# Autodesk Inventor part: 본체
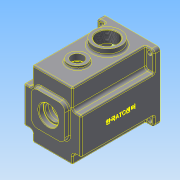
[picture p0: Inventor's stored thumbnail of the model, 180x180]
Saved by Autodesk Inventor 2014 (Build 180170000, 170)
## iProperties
Created: 2016-02
Part Number: 본체
Material: 알루미늄 6061
Document SubType Name: Modeling
Designer: mduedu
Density: 2.71 g/cm^3
Mass: 1353.73 g
Surface Area: 1142.22 cm^2
Volume: 499.531 cm^3
Appearance: 기본값
Author: mduedu
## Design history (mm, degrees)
sketch "스케치1"
  geometry: L1 (-47, -47)-(47, -47); L2 (47, -47)-(47, 63); L3 (47, 63)-(-47, 63); L4 (-47, 63)-(-47, -47); 2 further points
  constraints: 8 end point, 2 parallel, 1 horizontal, 1 midpoint, 1 perpendicular, 1 vertical alignment
  dimensions: "d0" = 94 distance of L2.end L3.end; "d155" = 110 distance of L1.end L2.end; "d156" = 47 distance from line of L1 point (0, 0)
extrude "돌출1" new body sketch "스케치1" distance "d2" = 130; taper "d3" = 0 deg
sketch "스케치3"
  geometry: C1 r 40 at (0, 0); 1 further point
  constraints: 1 centre point, 1 coincident
  dimensions: "d9" = 80 diameter of C1
extrude "돌출3" cut sketch "스케치3" distance "d11" = 121; taper "d12" = 0 deg
sketch "스케치4"
  geometry: C1 r 21 at (0, 11); 1 further point
  constraints: 1 centre point, 1 vertical alignment
  dimensions: "d13" = 21 radius of C1; "d15" = 11 distance of point (0, 0) C1.centre
extrude "돌출4" join sketch "스케치4" distance "d16" = 7; taper "d17" = 0 deg
sketch "스케치5"
  geometry: C1 r 15 at (0, -20); 1 further point
  constraints: 1 centre point, 1 vertical alignment
  dimensions: "d18" = 15 radius of C1; "d20" = 20 distance of point (0, 0) C1.centre
extrude "돌출5" join sketch "스케치5" distance "d21" = 7; taper "d22" = 0 deg
sketch "스케치6"
  geometry: L1 (-28, -17)-(28, -17); L2 (28, -17)-(28, 39); L3 (28, 39)-(-28, 39); L4 (-28, 39)-(-28, -17); L5 (-28, -17)-(28, 39); L6 (28, -17)-(-28, 39); C1 r 28 at (0, 11); A1 r 21 centre (0, 11) between (8.978, -7.984) and (-8.978, -7.984) reference; 1 further point
  constraints: 12 end point, 2 midpoint, 2 parallel, 2 tangent, 1 centre point, 1 coincident, 1 horizontal, 1 perpendicular
  dimensions: "d23" = 56 diameter of C1
extrude "돌출6" join sketch "스케치6" distance "d25" = 7; taper "d26" = -3 deg
hole "구멍1" diameter "d29" = 35; stored, may be unused: countersink angle "d33" = 90 deg, drill point angle "d35" = 0 deg; dims "d27" = 10, "d28" = 10, "d30" = 6, "d31" = 4, "d32" = 2, "d34" = 10
hole "구멍2" diameter "d38" = 22; stored, may be unused: countersink angle "d42" = 90 deg, drill point angle "d44" = 0 deg; dims "d36" = 10, "d37" = 10, "d39" = 6, "d40" = 4, "d41" = 2, "d43" = 7
hole "구멍3" diameter "d47" = 19; stored, may be unused: countersink angle "d51" = 90 deg, drill point angle "d53" = 0 deg; dims "d45" = 10, "d46" = 10, "d48" = 6, "d49" = 4, "d50" = 2, "d52" = 1
hole "구멍4" diameter "d56" = 32; stored, may be unused: countersink angle "d60" = 90 deg, drill point angle "d62" = 0 deg; dims "d57" = 6, "d58" = 4, "d59" = 2, "d61" = 8, "d220" = 10, "d221" = 10
hole "구멍5" diameter "d65" = 25; stored, may be unused: countersink angle "d69" = 90 deg, drill point angle "d71" = 0 deg; dims "d63" = 10, "d64" = 10, "d66" = 6, "d67" = 4, "d68" = 2, "d70" = 8
fillet "모깎기2" dims "d73" = 0.3
fillet "모깎기3" dims "d74" = 2
chamfer "모따기1" distance "d75" = 1; stored, may be unused: second distance "d76" = 2, angle "d77" = 45 deg
fillet "모깎기4" dims "d78" = 3
sketch "스케치16"
  geometry: L1 (-23, 32.726)-(23, 32.726); L2 (23, 32.726)-(23, 53); L3 (23, 53)-(-23, 53); L4 (-23, 53)-(-23, 32.726); L5 (-47, 63)-(47, 63) reference; 3 further points
  constraints: 8 end point, 2 parallel, 1 horizontal, 1 midpoint, 1 perpendicular, 1 vertical alignment, 2 other
  dimensions: "d160" = 46 distance of L2.end L3.end; "d163" = 10 distance between parallel lines of L3 L5
extrude "돌출15" cut sketch "스케치16" stored distance "d164" = 10; taper "d165" = 0 deg
fillet "모깎기5" dims "d79" = 2
fillet "모깎기15" dims "d166" = 5
sketch "스케치7"
  geometry: L1 (-23, 48)-(-23, 35.228) reference; L2 (23, 35.228)-(23, 48) reference; L3 (18, 53)-(-18, 53) reference; L4 (47, 63)-(47, -47) reference; L5 (47, -47)-(-47, -47) reference; L6 (-47, -47)-(-47, 63) reference; L7 (-47, 63)-(47, 63) reference; L8 (-26, 48)-(-26, 35.228); L9 (26, 35.228)-(26, 48); L10 (18, 56)-(-18, 56); C1 r 43 at (0, 0); A1 r 5 centre (-18, 48) between (-18, 53) and (-23, 48) reference; A2 r 5 centre (-28, 35.228) between (-24.889, 31.314) and (-23, 35.228) reference; A3 r 40 centre (0, 0) between (-24.889, 31.314) and (24.889, 31.314) reference; A4 r 5 centre (28, 35.228) between (23, 35.228) and (24.889, 31.314) reference; A5 r 5 centre (18, 48) between (23, 48) and (18, 53) reference; A6 r 8 centre (-18, 48) between (-18, 56) and (-26, 48); A7 r 2 centre (-28, 35.228) between (-26.756, 33.662) and (-26, 35.228); A8 r 43 centre (0, 0) between (-26.756, 33.662) and (26.756, 33.662); A9 r 2 centre (28, 35.228) between (26, 35.228) and (26.756, 33.662); A10 r 8 centre (18, 48) between (26, 48) and (18, 56); 1 further point
  constraints: 10 point on circle, 6 centre point, 6 end point, 1 coincident, 7 other
  dimensions: "d80" = 86 diameter of C1; "d167" = 3 distance between parallel lines of L3 L10
extrude "돌출7" cut sketch "스케치7" distance "d83" = 9; taper "d84" = 0 deg
sketch "스케치8" dims "d168" = 36
  geometry: L1 (-36, 4)-(-39.799, 4); L2 (-36, -4)-(-39.799, -4); A1 r 4 centre (-36, 0) between (-36, 4) and (-36, -4); A2 r 40 centre (0, 0) between (-24.889, 31.314) and (24.889, 31.314) reference; A3 r 40 centre (0, 0) between (-39.799, 4) and (-39.799, -4); 2 further points
  constraints: 5 point on circle, 4 end point, 2 centre point, 2 coincident, 2 horizontal alignment, 2 tangent, 1 horizontal, 1 parallel, 2 other
  dimensions: "d169" = 4 radius of A1
extrude "돌출9" join sketch "스케치8" stored distance "d89" = 9; taper "d90" = 0 deg
fillet "모깎기6" dims "d91" = 3.5
node "작업 평면1"
sketch "스케치9"
  geometry: L1 (47, 63)-(33, 63); L2 (33, 63)-(33, 30); L3 (33, 30)-(47, 30); L4 (47, 30)-(47, 63); L5 (47, 63)-(-47, 63) reference; L6 (47, -47)-(47, 63) reference; A1 r 40 centre (0, 0) between (-39.148, -8.214) and (39.148, -8.214) reference; 1 further point
  constraints: 8 end point, 2 parallel, 1 coincident, 1 horizontal, 1 perpendicular
  dimensions: "d95" = 33 distance from line of L2 point (0, 0); "d96" = 30 distance from line of L3 point (0, 0)
extrude "돌출10" cut sketch "스케치9" distance "d97" = 110; taper "d98" = 0 deg
extrude "돌출21" cut sketch "스케치9" stored distance "d217" = 10; taper "d218" = 0 deg
sketch "스케치11" dims "d20" = 20
  geometry: L1 (-40, -40)-(40, -40); L2 (40, -40)-(40, 56); L3 (40, 56)-(-40, 56); L4 (-40, 56)-(-40, -40); L5 (-47, -47)-(47, -47) reference; L6 (47, 63)-(-47, 63) reference; L7 (-47, 63)-(-47, -47) reference; C1 r 3.5 at (-40, 56); C2 r 3.5 at (40, 56); C3 r 3.5 at (40, -40); C4 r 3.5 at (-40, -40); 1 further point
  constraints: 8 end point, 4 centre point, 4 coincident, 3 equal radius, 2 parallel, 1 horizontal, 1 perpendicular
  dimensions: "d109" = 80 distance of L2.end L3.end; "d112" = 7 diameter of C1; "d157" = 7 distance from line of L1.start L5; "d158" = 7 distance between parallel lines of L6 L3; "d159" = 7 distance from line of L7 L3.end
extrude "돌출12" cut sketch "스케치11" stored distance "d113" = 63; taper "d114" = 0 deg
fillet "모깎기7" dims "d115" = 5, "d187" = 5
fillet "모깎기8" dims "d116" = 5
fillet "모깎기18" dims "d219" = 2
fillet "모깎기12" dims "d120" = 2
fillet "모깎기13" dims "d121" = 2
sketch "스케치12"
  geometry: 3 further points
  constraints: 2 horizontal alignment
hole "구멍6" sketch "스케치12" at (36, 0), (-36, 0) diameter "d122" = 3.242; stored, may be unused: countersink angle "d126" = 90 deg, drill point angle "d128" = 120 deg; dims "d123" = 7, "d124" = 4, "d125" = 2, "d127" = 9
fillet "모깎기14" dims "d147" = 10
chamfer "모따기4" distance "d151" = 1; stored, may be unused: second distance "d152" = 2, angle "d153" = 45 deg
sketch "스케치20"
  geometry: L1 (73, -12)-(73, -130) reference; L2 (84, -8)-(77, -8) reference; L3 (84, 0)-(84, -8) reference; L4 (84, 0)-(0, 0) reference; L5 (7, -8)-(0, -8) reference; L6 (11, -130)-(11, -12) reference; L7 (0, -8)-(0, 0) reference; L8 (73, -130)-(11, -130) reference; L9 (42, 0)-(42, -130); C1 r 10 at (42, -89); A1 r 4 centre (77, -12) between (77, -8) and (73, -12) reference; A2 r 4 centre (7, -12) between (11, -12) and (7, -8) reference
  constraints: 2 end point, 1 centre point, 1 midpoint, 1 point on line
  dimensions: "d189" = 20 diameter of C1; "d190" = 41 distance from line of C1.centre L8
extrude "돌출19" cut sketch "스케치20" stored distance "d191" = 10; taper "d192" = 0 deg
sketch "스케치18"
  geometry: C1 r 15 at (42, -89); C2 r 10 at (42, -89) reference; 1 further point
  constraints: 1 centre point, 1 concentric
  dimensions: "d174" = 30 diameter of C1
extrude "돌출17" join sketch "스케치18" distance "d175" = 5; taper "d176" = 0 deg
fillet "모깎기16" dims "d177" = 2
sketch "스케치19"
  geometry: C1 r 10 at (18, 80) reference; C2 r 15 at (18, 80); 1 further point
  constraints: 1 centre point, 1 coincident
  dimensions: "d178" = 30 diameter of C2
extrude "돌출18" cut sketch "스케치19" distance "d181" = 5; taper "d182" = 0 deg
chamfer "모따기5" distance "d183" = 0.5; stored, may be unused: second distance "d184" = 2, angle "d185" = 45 deg
sketch "스케치21"
  geometry: L1 (-12, 14)-(-130, 14) reference; L2 (-8, 0)-(-8, 10) reference; L3 (0, 0)-(0, 100) reference; L4 (-8, 100)-(0, 100) reference; L5 (-8, 74)-(-8, 100) reference; L6 (-130, 70)-(-12, 70) reference; L7 (-130, 14)-(-130, 70) reference; L8 (0, 0)-(-8, 0) reference; L9 (-130, 14)-(-130, 70) reference; L10 (27.4, 42)-(-164.4, 42) reference; A1 r 4 centre (-12, 74) between (-12, 70) and (-8, 74) reference; A2 r 4 centre (-12, 10) between (-8, 10) and (-12, 14) reference; 3 further points
  constraints: 1 coincident, 1 point on line, 1 other
  dimensions: "d222" = 65 distance from line of point (-65, 42) L9
feature "엠보싱2" sketch "스케치21" dims "d20" = 20, "d193" = 0.5, "d194" = 0
sketch "스케치22"
  geometry: L1 (73, -12)-(73, -130) reference; L2 (84, -8)-(77, -8) reference; L3 (84, 0)-(84, -8) reference; L4 (84, 0)-(0, 0) reference; L5 (7, -8)-(0, -8) reference; L6 (11, -130)-(11, -12) reference; L7 (0, -8)-(0, 0) reference; L8 (73, -130)-(11, -130) reference; L9 (42, -130)-(42, 0); C1 r 17 at (42, -89) reference; C2 r 22.5 at (42, -40); A1 r 4 centre (77, -12) between (77, -8) and (73, -12) reference; A2 r 4 centre (7, -12) between (11, -12) and (7, -8) reference
  constraints: 2 end point, 1 centre point, 1 midpoint, 1 point on line
  dimensions: "d195" = 45 diameter of C2; "d197" = 40 distance from line of C2.centre L4
extrude "돌출20" join sketch "스케치22" distance "d198" = 10; taper "d199" = 0 deg
fillet "모깎기17" dims "d200" = 3
hole "구멍7" diameter "d203" = 33.376; stored, may be unused: countersink angle "d207" = 90 deg, drill point angle "d209" = 118 deg; dims "d204" = 6, "d205" = 4, "d206" = 2, "d208" = 8, "d223" = 10, "d224" = 10
chamfer "모따기6" distance "d210" = 1; stored, may be unused: second distance "d211" = 2, angle "d212" = 45 deg
fillet "모깎기19" dims "d225" = 2
node "솔리드1"
pattern_circular "원형 패턴1" dims angle "d93" = 360 deg
mirror "대칭1"
mirror "대칭2"
node "투영된 루프1"
node "투영된 루프2"
node "투영된 루프3"
node "절단 모서리 투영3"
